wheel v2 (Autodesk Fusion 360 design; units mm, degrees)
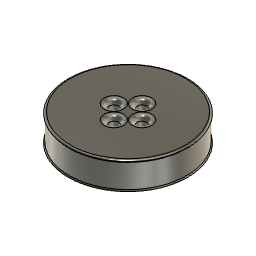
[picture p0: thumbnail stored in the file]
sketch "草图" plane through (0, 0, 0) normal (0, 0, 1) x axis (1, 0, 0)
  line L1 (0, 6) -> (0, 0)
  circle C1 centre (0, 0) radius 25
  circle C2 centre (0, 6) radius 1.125
  circle C3 centre (-6, 0) radius 1.125
  circle C4 centre (0, -6) radius 1.125
  circle C5 centre (6, 0) radius 1.125
  circle C6 centre (0, 6) radius 2.125
  circle C7 centre (6, 0) radius 2.125
  circle C8 centre (-6, 0) radius 2.125
  circle C9 centre (0, -6) radius 2.125
  circle C10 centre (0, 0) radius 25.5
  point P1 (0, 0)
  point P2 (0, 0)
  point P3 (0, 0)
  point P4 (0, 6)
  point P5 (0, 6)
  coincident P1 P2
  coincident P2 P3
  vertical L1
  coincident P4 P5
  dimension "d1" diameter C1 = 50
  dimension "d2" diameter C2 = 2.25
  dimension "d5" distance P3 P4 = 6
  dimension "d6" = 1
  dimension "d7" = 1
  dimension "d8" = 1
  dimension "d9" = 1
  dimension "d14" = 0.5
  dimension "d4" C-Pattern1-Angle = 360
extrude "拉伸1" new body sketch "草图" profile of C1 C6 C7 C8 C9 along normal blind 12
extrude "拉伸2" add sketch "草图" profile of C2 C3 C4 C5 C6 C7 C8 C9 along normal blind 3
extrude "拉伸3" add sketch "草图" profile of C1 C10 along normal blind 1
extrude "拉伸4" of existing geometry blind -1
fillet "圆角1" radius 1
chamfer "倒角" distance 0.5
fillet "圆角2" radius 2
